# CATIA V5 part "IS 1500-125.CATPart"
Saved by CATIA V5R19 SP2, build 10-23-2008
Part number: IS 1500-125
Bounding box of the stored display mesh (mm): x -37.351 to 37.351, y -37.351 to 37.351, z 0 to 360
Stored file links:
  C:\Users\Bora\Desktop\3D Katı model\IS serisi\IS 1500\IS 1500-125.CATPart
  C:\Program Files\Dassault Systemes\B19\intel_a\reffiles\standard\MetricThickPitch.txt
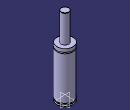
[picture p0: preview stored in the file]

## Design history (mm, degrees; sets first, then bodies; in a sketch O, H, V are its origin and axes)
Body1 (main body)
  Sketch1 on yz-plane, origin (0, 0, 0), H (0, 1, 0), V (0, 0, 1)
    point P1 (37.5, 216.5)
    point P2 (37.5, 211.5)
    point P5 (18, 359)
    point P7 (18, 359)
    point P12 (37.5, 211.5)
    point P13 (37.5, 216.5)
    arc A1 centre (37.5, 214) radius 2.5 from (37.5, 216.5) to (37.5, 211.5) ccw
    line L1 (37.5, 0) -> (37.5, 8)
    line L2 (18, 359) -> (18, 232)
    arc A2 centre (17, 359) radius 1 from (18, 359) to (17, 360) ccw
    line L3 (33.5, 13) -> (33.5, 8)
    line L4 (37.5, 13) -> (37.5, 211.5)
    line L5 (37.5, 216.5) -> (37.5, 232)
    line L6 (17, 360) -> (0, 360)
    point P15 (0, 360)
    line L7 (18, 232) -> (37.5, 232)
    line L8 (0, 0) -> (37.5, 0)
    line L9 (33.5, 8) -> (37.5, 8)
    line L10 (33.5, 13) -> (37.5, 13)
    coincidence: P15 V, P1 P13, P2 P12, P5 P7
    tangency: L6 A2
    horizontal: L7 H, L8 H, L9 H, L10 H
  Shaft1: profile Sketch1, axis Sketch1.V, angle 360
  Sketch2 on face of Shaft1 from Sketch1.L8, origin (0, 0, 0), H (1, 0, 0), V (0, -1, 0)
    point P1 (20, 0)
    distance P1 V = 20
  Hole1: placed by Sketch2, at (20, 0, 0) direction (0, 0, 1), diameter 6.647, depth 13, threaded "M8", thread diameter 8, thread depth 13, pitch 1.25
  CircPattern1: of Hole1, instances 4, angular step 90, axis from xy-plane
